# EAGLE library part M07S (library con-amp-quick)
AMP QUICK CONNECTOR
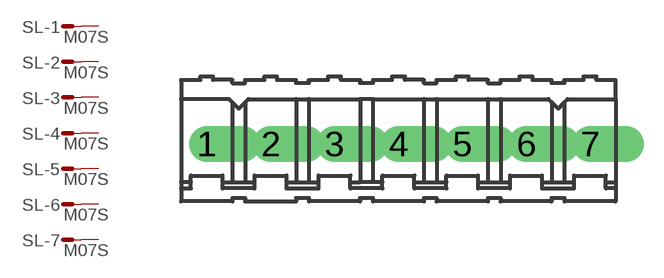
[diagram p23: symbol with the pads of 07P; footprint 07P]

Designator prefix SL; gates -1=M -2=M -3=M -4=M -5=M -6=M -7=M

## M07S  [07P]
1  -1:S  pas
2  -2:S  pas
3  -3:S  pas
4  -4:S  pas
5  -5:S  pas
6  -6:S  pas
7  -7:S  pas

## Footprint 07P (pad centres in mm)
AMP QUICK CONNECTOR
drill 0.914 offset: 1 -7.62,0; 2 -5.08,0; 3 -2.54,0; 4 0,0; 5 2.54,0; 6 5.08,0; 7 7.62,0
